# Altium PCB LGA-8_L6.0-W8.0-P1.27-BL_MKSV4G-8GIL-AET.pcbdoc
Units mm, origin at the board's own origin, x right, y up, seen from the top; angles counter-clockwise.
Board outline 18.73 x 22.2 mm, 2 copper layers (Top Layer, Bottom Layer), stack 0.07 mm thick; 1 components, 0 nets, 8 pads, 0 vias.
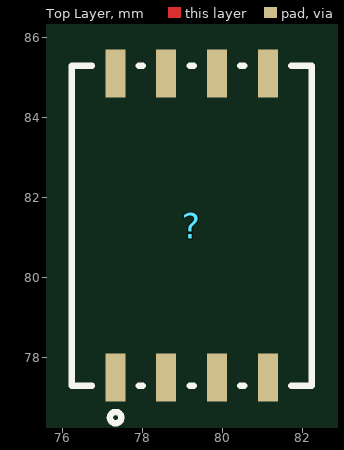
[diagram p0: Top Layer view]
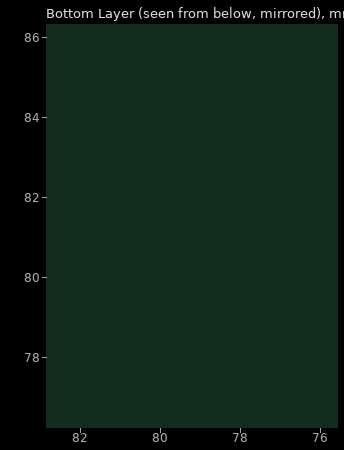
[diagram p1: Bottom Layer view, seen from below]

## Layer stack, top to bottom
Top Solder Mask Layer: solder mask 0.01, Dk 3.3
Top Layer: signal copper 0.035
Bottom Layer: signal copper 0.035
Bottom Solder Mask Layer: solder mask 0.01, Dk 3.3

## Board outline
88.58,69.85 69.85,69.85 69.85,92.05 88.58,92.05

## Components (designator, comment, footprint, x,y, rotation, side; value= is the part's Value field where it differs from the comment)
? "LGA-8_L6.0-W8.0-P1.27-BL_MKSV4G-8GIL-AET" LGA-8_L6.0-W8.0-P1.27-BL_MKSV4G-8GIL-AET 79.23,81.3 r0 top

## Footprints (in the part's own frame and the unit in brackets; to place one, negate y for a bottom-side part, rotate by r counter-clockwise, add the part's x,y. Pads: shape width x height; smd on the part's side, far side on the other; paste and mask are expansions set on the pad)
LGA-8_L6.0-W8.0-P1.27-BL_MKSV4G-8GIL-AET [mm]
  rect 0.5x1.2 smd paste+0 mask+0.05: 1(-1.905,-3.8) 2(-0.635,-3.8) 3(0.635,-3.8) 4(1.905,-3.8) 5(1.905,3.8) 6(0.635,3.8) 7(-0.635,3.8) 8(-1.905,3.8)
  silkscreen extent -3,-4.94 3,4

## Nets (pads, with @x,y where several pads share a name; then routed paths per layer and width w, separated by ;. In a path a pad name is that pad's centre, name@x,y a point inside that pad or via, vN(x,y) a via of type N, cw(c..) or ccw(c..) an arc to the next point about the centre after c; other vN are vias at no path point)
pads on no net: ?.1 ?.2 ?.3 ?.4 ?.5 ?.6 ?.7 ?.8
